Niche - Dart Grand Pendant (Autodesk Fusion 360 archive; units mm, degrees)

design "Dart Grand" references "PCB Single Pendant Canopy"
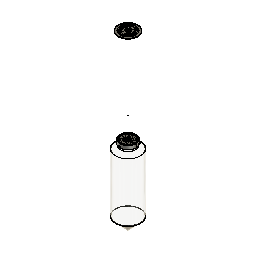
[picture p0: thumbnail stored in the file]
base_feature "Base Feature" bodies "Glass-Dart Grand"
external_derived "ExternalDerived1" bodies "Set Screw", "Strain Relief", "Lead-1", "Lead-2", "Lead-2.1", "Lead-1.1", "Coax", "Stem"
move "Move1"
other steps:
derived_base_feature "Derived Base Feature" bodies "Set Screw", "Strain Relief", "Lead-1", "Lead-2", "Lead-2.1", "Lead-1.1", "Coax", "Stem"
create_component "CreateComponent1"
named bodies: "Glass-Dart Grand", "Set Screw", "Strain Relief", "Lead-1", "Lead-2", "Lead-2.1", "Lead-1.1", "Coax", "Stem", "Strain Relief Cap", "Nylon Gripper (2)", "Cap", "Thumbscrew (1)", "Thumbscrew (2)", "Thumbscrew (3)", "Niche-PCB", "FJ-Plug Cover", "FJ-Plug", "FJ-Plug1.1", "FJ-Plug1.2", "FJ-Plug1.3", "Fj-Plug1.4", "Canopy", "FJ-Port", "FJ-Port1.1", "Spacer", "Universal Mount", "FJ-Port Cover", "Diffuser"

design "FJ Plug - PCB-Hardware"
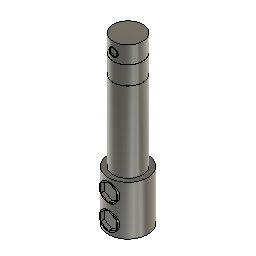
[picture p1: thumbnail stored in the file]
sketch "Sketch1" plane through (0, 0, 0) normal (0, 0, 1) x axis (1, 0, 0)
  circle C1 centre (0, 0) radius 3.048
  point P1 (0, 0)
  point P2 (0, 0)
  coincident P1 P2
  dimension "d1" diameter C1 = 6.096
extrude "Extrude1" new body sketch "Sketch1" along normal blind 34.036
sketch "Sketch2" plane through (0, 0, 0) normal (0, 0, 1) x axis (1, 0, 0)
  circle C1 centre (0, 0) radius 4.064
  point P1 (0, 0)
  point P2 (0, 0)
  coincident P1 P2
  dimension "d4" diameter C1 = 8.128
extrude "Extrude2" add sketch "Sketch2" along normal blind 10.16
sketch "Sketch3" plane through (0, 0, 0) normal (0, 1, 0) x axis (1, 0, 0)
  line L1 (6.35, 0) -> (-6.35, 0)
  line L2 (6.35, -30.48) -> (-6.35, -30.48)
  line L3 (2.54, -30.48) -> (6.35, -30.48)
  line L4 (2.54, -26.67) -> (2.54, -30.48)
  line L5 (6.35, -26.67) -> (2.54, -26.67)
  line L6 (6.35, -30.48) -> (6.35, -26.67)
  horizontal L1
  horizontal L3
  vertical L4
  horizontal L5
  vertical L6
  dimension "d7" = 30.48
revolve "Revolve1" sketch "Sketch3" AlongAngle 360
sketch "Sketch4" plane through (0, 0, 0) normal (0, 1, 0) x axis (1, 0, 0)
  line L1 (2.54, -30.48) -> (3.048, -30.48)
  line L2 (2.54, -26.67) -> (2.54, -30.48)
  line L3 (3.048, -26.67) -> (2.54, -26.67)
  line L4 (3.048, -30.48) -> (3.048, -26.67)
  horizontal L1
  vertical L2
  horizontal L3
  vertical L4
revolve "Revolve2" sketch "Sketch4" AlongAngle 360
chamfer "Chamfer1" distance 0.0254
chamfer "Chamfer2" distance 0.0254
hole "Hole1" HoleDepth 33.401 HoleDiameter 4.826 TipAngle 180
hole "Hole2" HoleDepth 3.81 HoleDiameter 1.778 TipAngle 180
hole "Hole3" HoleDepth 3.81 HoleDiameter 3.81 TipAngle 180
hole "Hole4" HoleDepth 3.81 HoleDiameter 3.81 TipAngle 180
sketch "Sketch5" plane through (0, 0, 0) normal (0, 1, 0) x axis (1, 0, 0)
  circle C1 centre (0, -32.0802) radius 0.889
  dimension "d24" diameter C1 = 1.778
extrude "Extrude3" new body sketch "Sketch5" along normal blind 1.778
move "Move1"
sketch "Sketch6" plane through (0, -3.048, 0) normal (0, -1, 0) x axis (1, 0, 0)
  line L1 (0.7259, 31.6611) -> (0, 31.242)
  line L2 (0.7259, 32.4993) -> (0.7259, 31.6611)
  line L3 (0, 32.9184) -> (0.7259, 32.4993)
  line L4 (-0.7259, 32.4993) -> (0, 32.9184)
  line L5 (-0.7259, 31.6611) -> (-0.7259, 32.4993)
  line L6 (0, 31.242) -> (-0.7259, 31.6611)
  circle C1 centre (0, 32.0802) radius 0.889
  point P2 (0, 32.0802)
  point P9 (0, 32.0802)
  coincident P2 P9
extrude "Extrude4" cut sketch "Sketch6" profile of L1 L2 L3 L4 L5 L6 against normal blind 0.254
sketch "Sketch7" plane through (0, 0, 0) normal (0, 1, 0) x axis (1, 0, 0)
  circle C1 centre (0, -2.4384) radius 1.905
  circle C2 centre (0, -7.5565) radius 1.905
  dimension "d29" diameter C1 = 3.81
  dimension "d30" diameter C2 = 3.81
extrude "Extrude5" new body sketch "Sketch7" profile of C2 along normal blind 3.81
move "Move2"
sketch "Sketch8" plane through (0, -4.064, 0) normal (0, -1, 0) x axis (1, 0, 0)
  line L1 (1.5948, 6.6357) -> (0, 5.715)
  line L2 (1.5948, 8.4772) -> (1.5948, 6.6357)
  line L3 (0, 9.398) -> (1.5948, 8.4772)
  line L4 (-1.5948, 8.4772) -> (0, 9.398)
  line L5 (-1.5948, 6.6357) -> (-1.5948, 8.4772)
  line L6 (0, 5.715) -> (-1.5948, 6.6357)
  circle C1 centre (0, 7.5565) radius 1.905
  point P2 (0, 7.5565)
  point P9 (0, 7.5565)
  coincident P2 P9
extrude "Extrude6" cut sketch "Sketch8" profile of L1 L2 L3 L4 L5 L6 against normal blind 0.762
copy_paste_bodies "CopyPasteBodies2"
move "Move4"
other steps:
base_feature "Base Feature"

design "Flask Petite"
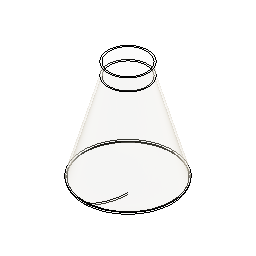
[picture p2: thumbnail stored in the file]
sketch "Sketch1" plane through (0, 0, 0) normal (1, 0, 0) x axis (0, 1, 0)
canvas "Canvas1"
sketch "Sketch2" plane through (0, 0, 0) normal (1, 0, 0) x axis (0, 1, 0)
  line L1 (-5.314, 187.093) -> (-57.384, 187.093)
  line L2 (-57.384, 155.343) -> (-57.384, 187.093)
  line L3 (-121.92, -71.12) -> (-57.384, 155.343)
  line L4 (-5.314, -112.5919) -> (-5.314, 187.093)
  curve K1 (-5.314, -112.5919) -> (-121.92, -74.8854)
  arc A1 centre (-115.3135, -73.0027) radius 6.8695 clockwise from (-121.92, -74.8854) to (-121.92, -71.12)
  point P2 (-57.384, 187.093)
  point P3 (-5.314, 187.093)
  point P4 (-57.384, 155.343)
  horizontal L1
  perpendicular L1 L2
  tangent L3 A1
  perpendicular L1 L4
  dimension "d1" distance P2 P3 = 52.07
  dimension "d2" distance P2 P4 = 31.75
revolve "Revolve1" sketch "Sketch2" AlongAngle 360
fillet "Fillet1" radius 5.08
shell "Shell1" innerThickness 4

design "PCB Single Pendant Canopy" references "Flask Petite", "FJ Cover - PCB-Hardware", "PCB Cap", "PCB Canopy", "Diffuser", "FJ Plug - PCB-Hardware"
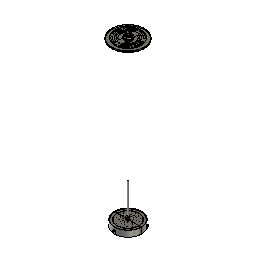
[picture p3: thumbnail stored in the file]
external_derived "ExternalDerived1" bodies "Nylon Gripper", "Set Screw", "Strain Relief", "Lead-1", "Lead-2", "Lead-2.1", "Lead-1.1", "Coax"
external_derived "ExternalDerived2" bodies "FJ-Plug Cover"
move "Move1"
move "Move2" TranslateX 3.175 TranslateY 0.254 TranslateZ 0
move "Move3" TranslateX 0 TranslateY 0 TranslateZ 1092.2
external_derived "ExternalDerived3" bodies "FJ-Plug", "FJ-Plug1.2", "FJ-Plug1.1", "FJ-Plug1.3", "Fj-Plug1.4"
move "Move4" TranslateX 0 TranslateY 0 TranslateZ 1117.6
external_derived "ExternalDerived4" bodies "Nylon Gripper", "Spacer", "Canopy", "FJ-Port", "FJ-Port1.1", "Universal Mount", "FJ-Port Cover", "Lead-1.1"
move "Move5"
move "Move6"
external_derived "ExternalDerived5" bodies "Diffuser"
move "Move7"
external_derived "ExternalDerived6" bodies "Thumbscrew (1)"
align "Align1"
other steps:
derived_base_feature "Derived Base Feature1"
derived_base_feature "Derived Base Feature2" bodies "FJ-Plug Cover"
derived_base_feature "Derived Base Feature3" bodies "FJ-Plug", "FJ-Plug1.1", "FJ-Plug1.2"
derived_base_feature "Derived Base Feature4" bodies "Body1 (1)", "Body1 (1) (1)", "Body2 (1)", "Body1 (2)", "Body1 (3)", "Body1 (4)", "Canopy", "FJ-Port"
derived_base_feature "Derived Base Feature5" bodies "Diffuser"
derived_base_feature "Derived Base Feature6" bodies "Body1", "Thumbscrew (1)"
named bodies: "Nylon Gripper", "Set Screw", "Strain Relief", "Lead-1", "Lead-2", "Lead-2.1", "Lead-1.1", "Coax", "Stem", "stem (2)", "Strain Relief Cap", "Nylon Gripper (2)", "Cap", "Thumbscrew (1)", "Thumbscrew (2)", "Thumbscrew (3)", "Niche-PCB", "FJ-Plug Cover", "FJ-Plug", "FJ-Plug1.1", "FJ-Plug1.2", "FJ-Plug1.3", "Fj-Plug1.4", "Body1 (1)", "Body1 (1) (1)", "Body2 (1)", "Body1 (2)", "Body1 (3)", "Body1 (4)", "Canopy", "FJ-Port", "FJ-Port1.1", "Spacer", "Universal Mount", "FJ-Port Cover", "Diffuser", "Body1"

design "FJ Female"
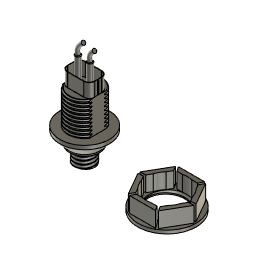
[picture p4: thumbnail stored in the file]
sketch "Sketch1" plane through (0, 0, 0) normal (0, 0, 1) x axis (1, 0, 0)
  circle C1 centre (0, 0) radius 4.445
  point P1 (0, 0)
  point P2 (0, 0)
  coincident P1 P2
  dimension "d1" diameter C1 = 8.89
extrude "Extrude1" new body sketch "Sketch1" along normal blind 6.858
sketch "Sketch2" plane through (0, 0, 6.858) normal (0, 0, 1) x axis (-1, 0, 0)
  circle C1 centre (0, 0) radius 4.445
  circle C2 centre (0, 0) radius 6.985
  point P1 (0, 0)
  point P3 (0, 0)
  coincident P1 P3
  dimension "d4" diameter C2 = 13.97
extrude "Extrude2" add sketch "Sketch2" along normal blind 1.27
work_plane "WorkPlane1" AlongDistance 5.08
sketch "Sketch3" plane through (0, 0, 13.208) normal (0, 0, 1) x axis (1, 0, 0)
  circle C1 centre (0, 0) radius 11.43
  point P1 (0, 0)
  point P2 (0, 0)
  coincident P1 P2
  dimension "d8" diameter C1 = 22.86
loft "Loft1" sketch "Sketch3"
extrude "Extrude3" add of existing geometry blind 1.778
sketch "Sketch4" plane through (0, 0, 14.986) normal (0, 0, 1) x axis (-1, 0, 0)
  circle C1 centre (0, 0) radius 11.43
  circle C2 centre (0, 0) radius 7.62
  point P1 (0, 0)
  point P3 (0, 0)
  coincident P1 P3
  dimension "d11" diameter C2 = 15.24
extrude "Extrude4" add sketch "Sketch4" profile of C2 along normal blind 15.24
sketch "Sketch5" plane through (0, 0, 30.226) normal (0, 0, 1) x axis (-1, 0, 0)
  line L1 (6.35, 0) -> (0, 0)
  line L2 (-6.35, 0) -> (0, 0)
  line L3 (6.35, -4.2121) -> (6.35, 0)
  line L4 (6.35, 4.2121) -> (6.35, 0)
  line L5 (-6.35, -4.2121) -> (-6.35, 0)
  line L6 (-6.35, 4.2121) -> (-6.35, 0)
  circle C1 centre (0, 0) radius 7.62
  point P2 (0, 0)
  point P3 (0, 0)
  point P5 (0, 0)
  point P7 (6.35, -4.2121)
  point P8 (6.35, 4.2121)
  point P9 (-6.35, -4.2121)
  point P10 (-6.35, 0)
  point P11 (-6.35, 4.2121)
  point P4 (6.35, 0)
  point P6 (-6.35, 0)
  coincident P2 P3
  horizontal L1
  coincident P2 P5
  parallel L1 L2
  coincident C1 P7
  perpendicular L1 L3
  coincident C1 P8
  perpendicular L1 L4
  coincident C1 P9
  perpendicular L2 L5
  coincident L2 P10
  perpendicular L2 L6
  coincident C1 P11
  dimension "d14" distance P3 P4 = 6.35
  dimension "d15" distance P5 P6 = 6.35
extrude "Extrude5" cut sketch "Sketch5" profile of C1 L3 L4 L5 L6 against normal blind 15.24
sketch "Sketch6" plane through (0, 0, 30.226) normal (0, 0, 1) x axis (-1, 0, 0)
  line L1 (-6.35, -4.2121) -> (-6.35, 4.2121)
  line L2 (6.35, 4.2121) -> (6.35, -4.2121)
  line L3 (-6.35, -4.2121) -> (6.35, -4.2121)
  line L4 (6.35, 4.2121) -> (-6.35, 4.2121)
  line L5 (6.35, -4.2121) -> (6.35, 4.2121)
  line L6 (-6.35, 4.2121) -> (-6.35, -4.2121)
  line L7 (-6.223, 4.064) -> (6.223, 4.064)
  line L8 (-6.223, -4.064) -> (-6.223, 4.064)
  line L9 (6.223, -4.064) -> (-6.223, -4.064)
  line L10 (6.223, 4.064) -> (6.223, -4.064)
  line L11 (-6.223, -4.064) -> (6.223, 4.064)
  line L12 (6.223, -4.064) -> (-6.223, 4.064)
  arc A1 centre (0, 0) radius 7.62 clockwise from (6.35, -4.2121) to (-6.35, -4.2121)
  arc A2 centre (0, 0) radius 7.62 clockwise from (-6.35, 4.2121) to (6.35, 4.2121)
  point P4 (6.35, -4.2121)
  point P7 (6.35, -4.2121)
  point P3 (-6.35, -4.2121)
  point P8 (-6.35, -4.2121)
  point P2 (-6.35, 4.2121)
  point P9 (-6.35, 4.2121)
  point P6 (6.35, 4.2121)
  point P10 (6.35, 4.2121)
  point P15 (0, 0)
  point P5 (0, 0)
  point P13 (-6.223, -4.064)
  point P14 (6.223, -4.064)
  point P12 (-6.223, 4.064)
  coincident P4 P7
  coincident P3 P8
  coincident P2 P9
  coincident P6 P10
  perpendicular L7 L8
  parallel L7 L9
  parallel L8 L10
  horizontal L7
  coincident L11 P15
  coincident L12 P15
  coincident P5 P15
  dimension "d18" distance P13 P14 = 12.446
  dimension "d19" distance P12 P13 = 8.128
extrude "Extrude6" add sketch "Sketch6" profile of L1 L2 L3 L4 L5 L6 L7 L8 L9 L10 along normal blind 6.35
fillet "Fillet1" radius 2.54
sketch "Sketch7" plane through (6.35, 0, 0) normal (1, 0, 0) x axis (0, 1, 0)
  line L1 (1.6721, 36.576) -> (1.6721, 30.226)
  line L2 (-1.6721, 36.576) -> (1.6721, 36.576)
  line L3 (-1.6721, 30.226) -> (-1.6721, 36.576)
  line L4 (-4.2121, 30.226) -> (-1.6721, 30.226)
  line L5 (-4.2121, 14.986) -> (-4.2121, 30.226)
  line L6 (4.2121, 14.986) -> (-4.2121, 14.986)
  line L7 (4.2121, 30.226) -> (4.2121, 14.986)
  line L8 (1.6721, 30.226) -> (4.2121, 30.226)
  line L9 (0.254, 36.576) -> (-0.2492, 36.576)
  line L10 (0.254, 30.226) -> (0.254, 36.576)
  line L11 (-0.2492, 30.226) -> (0.254, 30.226)
  line L12 (-0.2492, 36.576) -> (-0.2492, 30.226)
  point P10 (-0.2492, 36.576)
  horizontal L9
  vertical L10
  horizontal L11
  vertical L12
  coincident L2 P10
extrude "Extrude7" cut sketch "Sketch7" profile of L2 L9 L10 L11 L12 against normal blind 0.508
thread "Thread1"
fillet "Fillet2" radius 0.635
thread "Thread2"
sketch "Sketch8" plane through (0, 0, 30.226) normal (0, 0, 1) x axis (-1, 0, 0)
  line L1 (-6.223, -1.524) -> (-6.223, -0.254)
  line L2 (3.683, -4.064) -> (-3.683, -4.064)
  line L3 (6.223, 1.524) -> (6.223, -1.524)
  line L4 (-3.683, 4.064) -> (3.683, 4.064)
  line L5 (-6.223, 0.2492) -> (-6.223, 1.524)
  line L6 (-6.35, 0.2492) -> (-6.223, 0.2492)
  line L7 (-6.35, -0.254) -> (-6.35, 0.2492)
  line L8 (-6.223, -0.254) -> (-6.35, -0.254)
  arc A1 centre (-3.683, -1.524) radius 2.54 clockwise from (-3.683, -4.064) to (-6.223, -1.524)
  arc A2 centre (3.683, -1.524) radius 2.54 clockwise from (6.223, -1.524) to (3.683, -4.064)
  arc A3 centre (3.683, 1.524) radius 2.54 clockwise from (3.683, 4.064) to (6.223, 1.524)
  arc A4 centre (-3.683, 1.524) radius 2.54 clockwise from (-6.223, 1.524) to (-3.683, 4.064)
  circle C1 centre (3.048, 0) radius 1.27
  circle C2 centre (-2.54, 0) radius 1.27
  dimension "d26" diameter C1 = 2.54
  dimension "d27" diameter C2 = 2.54
extrude "Extrude8" add sketch "Sketch8" profile of C1 C2 along normal blind 11.43
sketch "Sketch9" plane through (0, 0, 0) normal (0, 1, 0) x axis (1, 0, 0)
  curve K1 (4.572, -46.99) -> (2.54, -41.656)
  curve K2 (-0.508, -47.752) -> (-3.048, -41.656)
pipe "Pipe1" SectionSize 1.778 SectionThickness 0.0762
pipe "Pipe2" SectionSize 1.778 SectionThickness 0.0762
sketch "Sketch10" plane through (0, 0, 0) normal (0, 0, 1) x axis (1, 0, 0)
  circle C1 centre (38.1, 0) radius 13.462
  dimension "d38" diameter C1 = 26.924
extrude "Extrude9" new body sketch "Sketch10" along normal blind 1.524
sketch "Sketch11" plane through (0, 0, 1.524) normal (0, 0, 1) x axis (-1, 0, 0)
  circle C1 centre (-38.1, 0) radius 13.462
  circle C2 centre (-38.1, 0) radius 9.271
  concentric C1 C2
  dimension "d41" diameter C2 = 18.542
extrude "Extrude10" cut sketch "Sketch11" profile of C2 against normal blind 7.62
sketch "Sketch12" plane through (0, 0, 1.524) normal (0, 0, 1) x axis (-1, 0, 0)
  line L1 (-24.9018, 0) -> (-31.5009, -11.43)
  line L2 (-31.5009, 11.43) -> (-24.9018, 0)
  line L3 (-44.6991, 11.43) -> (-31.5009, 11.43)
  line L4 (-51.2982, 0) -> (-44.6991, 11.43)
  line L5 (-44.6991, -11.43) -> (-51.2982, 0)
  line L6 (-31.5009, -11.43) -> (-44.6991, -11.43)
  line L7 (-27.3948, 0) -> (-32.7474, -9.271)
  line L8 (-32.7474, 9.271) -> (-27.3948, 0)
  line L9 (-43.4526, 9.271) -> (-32.7474, 9.271)
  line L10 (-48.8052, 0) -> (-43.4526, 9.271)
  line L11 (-43.4526, -9.271) -> (-48.8052, 0)
  line L12 (-32.7474, -9.271) -> (-43.4526, -9.271)
  circle C1 centre (-38.1, 0) radius 9.271
  circle C2 centre (-38.1, 0) radius 13.462
  point P2 (-38.1, 0)
  point P9 (-38.1, 0)
  point P16 (-38.1, 0)
  coincident P2 P9
  coincident P9 P16
extrude "Extrude11" add sketch "Sketch12" profile of L1 L2 L3 L4 L5 L6 L7 L8 L9 L10 L11 L12 along normal blind 7.112
thread "Thread3"
sketch "Sketch13" plane through (0, 0, 8.636) normal (0, 0, 1) x axis (-1, 0, 0)
  line L1 (-43.4526, -9.271) -> (-32.7474, -9.271)
  line L2 (-48.8052, 0) -> (-43.4526, -9.271)
  line L3 (-43.4526, 9.271) -> (-48.8052, 0)
  line L4 (-32.7474, 9.271) -> (-43.4526, 9.271)
  line L5 (-27.3948, 0) -> (-32.7474, 9.271)
  line L6 (-32.7474, -9.271) -> (-27.3948, 0)
  line L7 (-31.5009, -11.43) -> (-44.6991, -11.43)
  line L8 (-24.9018, 0) -> (-31.5009, -11.43)
  line L9 (-31.5009, 11.43) -> (-24.9018, 0)
  line L10 (-44.6991, 11.43) -> (-31.5009, 11.43)
  line L11 (-51.2982, 0) -> (-44.6991, 11.43)
  line L12 (-44.6991, -11.43) -> (-51.2982, 0)
sketch "Sketch14" plane through (0, 0, 8.636) normal (0, 0, 1) x axis (-1, 0, 0)
  circle C1 centre (-38.1, 0) radius 9.525
  dimension "d46" diameter C1 = 19.05
extrude "Extrude12" cut sketch "Sketch14" against normal blind 7.112
sketch "Sketch15" plane through (0, 0, 8.636) normal (0, 0, 1) x axis (-1, 0, 0)
  line L1 (-51.2982, 0) -> (-44.6991, 11.43)
  line L2 (-43.4526, 9.271) -> (-48.8052, 0)
  line L3 (-32.7474, 9.271) -> (-43.4526, 9.271)
  line L4 (-44.6991, 11.43) -> (-31.5009, 11.43)
  line L5 (-44.1911, 11.43) -> (-42.7995, 9.271)
  line L6 (-40.2139, 9.271) -> (-42.7995, 9.271)
  line L7 (-43.7181, 8.8112) -> (-45.0232, 10.8687)
  line L8 (-43.4526, 9.271) -> (-42.7995, 9.271)
  line L9 (-43.7181, 8.8112) -> (-43.4526, 9.271)
  line L10 (-45.0232, 10.8687) -> (-44.6991, 11.43)
  line L11 (-44.1911, 11.43) -> (-44.6991, 11.43)
  line L12 (-48.5398, -0.4598) -> (-50.9742, -0.5613)
  line L13 (-48.5398, -0.4598) -> (-48.8052, 0)
  line L14 (-48.8052, 0) -> (-48.4787, 0.5657)
  line L15 (-51.0442, 0.4399) -> (-48.4787, 0.5657)
  line L16 (-51.0442, 0.4399) -> (-51.2982, 0)
  line L17 (-50.9742, -0.5613) -> (-51.2982, 0)
  line L18 (-42.9217, -9.271) -> (-44.051, -11.43)
  line L19 (-42.9217, -9.271) -> (-43.4526, -9.271)
  line L20 (-43.4526, -9.271) -> (-43.7792, -8.7053)
  line L21 (-44.9531, -10.9901) -> (-43.7792, -8.7053)
  line L22 (-44.9531, -10.9901) -> (-44.6991, -11.43)
  line L23 (-44.051, -11.43) -> (-44.6991, -11.43)
  line L24 (-32.4819, -8.8112) -> (-31.1768, -10.8687)
  line L25 (-32.4819, -8.8112) -> (-32.7474, -9.271)
  line L26 (-32.7474, -9.271) -> (-33.4005, -9.271)
  line L27 (-32.0089, -11.43) -> (-33.4005, -9.271)
  line L28 (-32.0089, -11.43) -> (-31.5009, -11.43)
  line L29 (-31.1768, -10.8687) -> (-31.5009, -11.43)
  line L30 (-27.6603, 0.4598) -> (-25.2258, 0.5613)
  line L31 (-27.6603, 0.4598) -> (-27.3948, 0)
  line L32 (-27.3948, 0) -> (-27.7214, -0.5657)
  line L33 (-25.1558, -0.4399) -> (-27.7214, -0.5657)
  line L34 (-25.1558, -0.4399) -> (-24.9018, 0)
  line L35 (-25.2258, 0.5613) -> (-24.9018, 0)
  line L36 (-33.2783, 9.271) -> (-32.149, 11.43)
  line L37 (-33.2783, 9.271) -> (-32.7474, 9.271)
  line L38 (-32.7474, 9.271) -> (-32.4208, 8.7053)
  line L39 (-31.2469, 10.9901) -> (-32.4208, 8.7053)
  line L40 (-31.2469, 10.9901) -> (-31.5009, 11.43)
  line L41 (-32.149, 11.43) -> (-31.5009, 11.43)
  point P10 (-42.7995, 9.271)
  point P12 (-45.0232, 10.8687)
  point P13 (-43.7181, 8.8112)
  point P5 (-43.4526, 9.271)
  point P14 (-43.4526, 9.271)
  point P16 (-44.1911, 11.43)
  point P9 (-44.6991, 11.43)
  point P15 (-44.6991, 11.43)
  horizontal L6
  coincident L3 P10
  coincident L1 P12
  coincident L2 P13
  coincident P5 P14
  coincident L4 P16
  coincident P9 P15
  coincident L4 P16
  dimension "d50" distance P15 P16 = 0.508
  dimension "d54" C-Pattern1-Angle = 360
extrude "Extrude13" cut sketch "Sketch15" profile of L1 L2 L3 L4 L5 L7 L8 L9 L10 L11 L12 L13 L14 L15 L16 L17 L18 L19 L20 L21 L22 L23 L24 L25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 against normal blind 7.112

design "FJ Cover - PCB-Hardware"
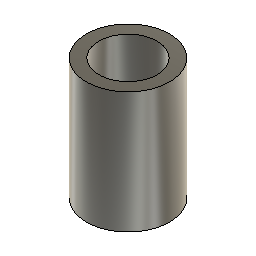
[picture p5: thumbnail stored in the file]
sketch "Sketch1" plane through (0, 0, 0) normal (0, 0, 1) x axis (1, 0, 0)
  circle C1 centre (0, 0) radius 6.35
  point P1 (0, 0)
  point P2 (0, 0)
  coincident P1 P2
  dimension "d1" diameter C1 = 12.7
extrude "Extrude1" new body sketch "Sketch1" along normal blind 18.542
hole "Hole1" HoleDepth 13.97 HoleDiameter 8.89 TipAngle 180
hole "Hole2" HoleDepth 13.97 HoleDiameter 3.556 TipAngle 180

design "PCB Canopy" references "Universal Mounting Bracket - PCB-Hardware", "FJ Female", "Canopy - PCB-Hardware", "Port Cover - PCB-Hardware", "FJ Cover - PCB-Hardware", "Spacer - PCB-Hardware"
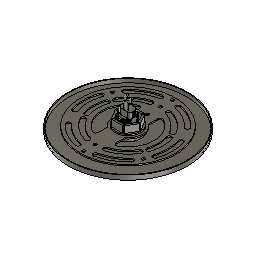
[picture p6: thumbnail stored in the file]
external_derived "ExternalDerived"
external_derived "ExternalDerived"
external_derived "ExternalDerived3" bodies "Body1 (1)"
external_derived "ExternalDerived4"
external_derived "ExternalDerived5"
move "Move1"
move "Move2"
move "Move3"
move "Move4"
move "Move5"
move "Move6"
move "Move7"
move "Move8"
external_derived "ExternalDerived6"
align "Align1"
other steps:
derived_base_feature "Derived Base Feature" bodies "Body1"
derived_base_feature "Derived Base Feature" bodies "Body1 (1)", "Body2"
derived_base_feature "Derived Base Feature3" bodies "Body1 (2)", "Body1 (1)"
derived_base_feature "Derived Base Feature4" bodies "Body1 (3)"
derived_base_feature "Derived Base Feature5" bodies "Body1 (4)"
derived_base_feature "Derived Base Feature6" bodies "Body1 (5)"
named bodies: "Body1", "Body1 (1)", "Body2", "Body1 (2)", "Body1 (3)", "Body1 (4)", "Body1 (5)"

design "Spacer - PCB-Hardware"
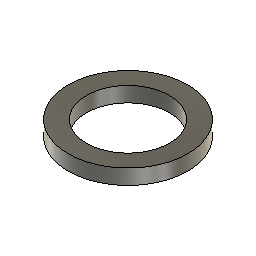
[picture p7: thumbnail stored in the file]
sketch "Sketch1" plane through (0, 0, 0) normal (0, 0, 1) x axis (1, 0, 0)
  circle C1 centre (0, 0) radius 14.097
  circle C2 centre (0, 0) radius 9.779
  point P1 (0, 0)
  point P2 (0, 0)
  point P3 (0, 0)
  coincident P1 P2
  coincident P1 P3
  dimension "d1" diameter C1 = 28.194
  dimension "d2" diameter C2 = 19.558
extrude "Extrude1" new body sketch "Sketch1" along normal blind 3.556

design "Universal Mounting Bracket - PCB-Hardware"
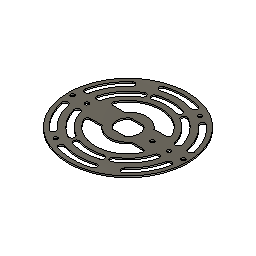
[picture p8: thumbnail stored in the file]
sketch "Sketch1" plane through (0, 0, 0) normal (0, 0, 1) x axis (1, 0, 0)
  circle C1 centre (0, 0) radius 50.8
  arc A1 centre (0, 0) radius 42.545 clockwise from (-13.1471, 40.4627) to (13.1471, 40.4627)
  arc A2 centre (0, 0) radius 47.371 clockwise from (-14.6384, 45.0525) to (14.6384, 45.0525)
  arc A3 centre (-13.8928, 42.7576) radius 2.413 clockwise from (-13.1471, 40.4627) to (-14.6384, 45.0525)
  arc A4 centre (13.8928, 42.7576) radius 2.413 clockwise from (14.6384, 45.0525) to (13.1471, 40.4627)
  arc A5 centre (0, 0) radius 47.371 clockwise from (-46.3358, 9.849) to (-31.6974, 35.2035)
  arc A6 centre (0, 0) radius 42.545 clockwise from (-41.6153, 8.8456) to (-28.4682, 31.6171)
  arc A7 centre (-43.9756, 9.3473) radius 2.413 clockwise from (-41.6153, 8.8456) to (-46.3358, 9.849)
  arc A8 centre (-30.0828, 33.4103) radius 2.413 clockwise from (-31.6974, 35.2035) to (-28.4682, 31.6171)
  arc A9 centre (0, 0) radius 47.371 clockwise from (-31.6974, -35.2035) to (-46.3358, -9.849)
  arc A10 centre (0, 0) radius 42.545 clockwise from (-28.4682, -31.6171) to (-41.6153, -8.8456)
  arc A11 centre (-30.0828, -33.4103) radius 2.413 clockwise from (-28.4682, -31.6171) to (-31.6974, -35.2035)
  arc A12 centre (-43.9756, -9.3473) radius 2.413 clockwise from (-46.3358, -9.849) to (-41.6153, -8.8456)
  arc A13 centre (0, 0) radius 47.371 clockwise from (14.6384, -45.0525) to (-14.6384, -45.0525)
  arc A14 centre (0, 0) radius 42.545 clockwise from (13.1471, -40.4627) to (-13.1471, -40.4627)
  arc A15 centre (13.8928, -42.7576) radius 2.413 clockwise from (13.1471, -40.4627) to (14.6384, -45.0525)
  arc A16 centre (-13.8928, -42.7576) radius 2.413 clockwise from (-14.6384, -45.0525) to (-13.1471, -40.4627)
  arc A17 centre (0, 0) radius 47.371 clockwise from (46.3358, -9.849) to (31.6974, -35.2035)
  arc A18 centre (0, 0) radius 42.545 clockwise from (41.6153, -8.8456) to (28.4682, -31.6171)
  arc A19 centre (43.9756, -9.3473) radius 2.413 clockwise from (41.6153, -8.8456) to (46.3358, -9.849)
  arc A20 centre (30.0828, -33.4103) radius 2.413 clockwise from (31.6974, -35.2035) to (28.4682, -31.6171)
  arc A21 centre (0, 0) radius 47.371 clockwise from (31.6974, 35.2035) to (46.3358, 9.849)
  arc A22 centre (0, 0) radius 42.545 clockwise from (28.4682, 31.6171) to (41.6153, 8.8456)
  arc A23 centre (30.0828, 33.4103) radius 2.413 clockwise from (28.4682, 31.6171) to (31.6974, 35.2035)
  arc A24 centre (43.9756, 9.3473) radius 2.413 clockwise from (46.3358, 9.849) to (41.6153, 8.8456)
  arc A25 centre (0, 0) radius 32.385 clockwise from (-31.2224, 8.5995) to (-16.1925, 28.0462)
  arc A26 centre (0, 0) radius 37.338 clockwise from (-35.9514, 10.0809) to (-18.669, 32.3357)
  arc A27 centre (0, 0) radius 32.385 clockwise from (16.1925, 28.0462) to (31.2224, 8.5995)
  arc A28 centre (0, 0) radius 32.385 clockwise from (-10.0075, 30.8) to (10.0075, 30.8)
  arc A29 centre (0, 0) radius 37.338 clockwise from (18.669, 32.3357) to (35.9514, 10.0809)
  arc A30 centre (0, 0) radius 37.338 clockwise from (-11.5381, 35.5105) to (11.5381, 35.5105)
  arc A31 centre (-33.5467, 9.4685) radius 2.4814 clockwise from (-31.1111, 8.9939) to (-35.9167, 10.2037)
  arc A32 centre (-17.4307, 30.1909) radius 2.4765 clockwise from (-18.669, 32.3357) to (-16.1925, 28.0462)
  arc A33 centre (-10.7728, 33.1553) radius 2.4765 clockwise from (-10.0075, 30.8) to (-11.5381, 35.5105)
  arc A34 centre (10.7728, 33.1553) radius 2.4765 clockwise from (11.5381, 35.5105) to (10.0075, 30.8)
  arc A35 centre (17.4307, 30.1909) radius 2.4765 clockwise from (16.1925, 28.0462) to (18.669, 32.3357)
  arc A36 centre (33.5467, 9.4685) radius 2.4814 clockwise from (35.9167, 10.2037) to (31.1111, 8.9939)
  arc A37 centre (-33.5467, -9.4685) radius 2.4814 clockwise from (-35.9167, -10.2037) to (-31.1111, -8.9939)
  arc A38 centre (0, 0) radius 37.338 clockwise from (-18.669, -32.3357) to (-35.9514, -10.0809)
  arc A39 centre (0, 0) radius 32.385 clockwise from (-16.1925, -28.0462) to (-31.2224, -8.5995)
  arc A40 centre (-17.4307, -30.1909) radius 2.4765 clockwise from (-16.1925, -28.0462) to (-18.669, -32.3357)
  arc A41 centre (-10.7728, -33.1553) radius 2.4765 clockwise from (-11.5381, -35.5105) to (-10.0075, -30.8)
  arc A42 centre (0, 0) radius 37.338 clockwise from (11.5381, -35.5105) to (-11.5381, -35.5105)
  arc A43 centre (0, 0) radius 32.385 clockwise from (10.0075, -30.8) to (-10.0075, -30.8)
  arc A44 centre (10.7728, -33.1553) radius 2.4765 clockwise from (10.0075, -30.8) to (11.5381, -35.5105)
  arc A45 centre (17.4307, -30.1909) radius 2.4765 clockwise from (18.669, -32.3357) to (16.1925, -28.0462)
  arc A46 centre (0, 0) radius 37.338 clockwise from (35.9514, -10.0809) to (18.669, -32.3357)
  arc A47 centre (0, 0) radius 32.385 clockwise from (31.2224, -8.5995) to (16.1925, -28.0462)
  arc A48 centre (33.5467, -9.4685) radius 2.4814 clockwise from (31.1111, -8.9939) to (35.9167, -10.2037)
  point P1 (0, 0)
  point P2 (0, 0)
  point P71 (-35.9514, 10.0809)
  point P72 (-31.2224, 8.5995)
  point P73 (35.9514, 10.0809)
  point P74 (31.2224, 8.5995)
  point P75 (-31.1111, 8.9939)
  point P76 (-35.9167, 10.2037)
  point P77 (35.9167, 10.2037)
  point P78 (31.1111, 8.9939)
  coincident P1 P2
  concentric C1 A2
  concentric A1 A2
  concentric A17 A26
  concentric A25 A26
  concentric A25 A27
  concentric A26 A29
  concentric A27 A28
  concentric A29 A30
  coincident P71 A31
  coincident P72 A31
  coincident P73 A36
  coincident P74 A36
  coincident A25 P75
  coincident A26 P76
  coincident A29 P77
  coincident A27 P78
  dimension "d1" diameter C1 = 101.6
  dimension "d2" diameter A2 = 94.742
  dimension "d11" diameter A26 = 74.676
  dimension "d12" diameter A25 = 64.77
  dimension "d10" C-Pattern1-Angle = 360
sketch "Sketch2" plane through (0, 0, 0) normal (0, 0, 1) x axis (1, 0, 0)
  line L1 (5.3986, -8.001) -> (-5.3986, -8.001)
  line L2 (5.3986, 8.001) -> (-5.3986, 8.001)
  arc A1 centre (0, 0) radius 9.652 clockwise from (-5.3986, -8.001) to (-5.3986, 8.001)
  arc A2 centre (0, 0) radius 9.652 clockwise from (5.3986, 8.001) to (5.3986, -8.001)
  point P1 (0, 0)
  point P2 (0, 0)
  coincident P1 P2
  concentric A1 A2
  dimension "d6" diameter A1 = 19.304
sketch "Sketch3" plane through (0, 0, 0) normal (0, 0, 1) x axis (1, 0, 0)
  line L1 (-12.5409, 9.525) -> (-22.2072, 9.525)
  line L2 (22.2072, 9.525) -> (12.5409, 9.525)
  line L3 (-12.5409, -9.525) -> (-22.2072, -9.525)
  line L4 (22.2072, -9.525) -> (12.5409, -9.525)
  arc A1 centre (0, 0) radius 15.748 clockwise from (12.5409, -9.525) to (-12.5409, -9.525)
  arc A2 centre (0, 0) radius 15.748 clockwise from (-12.5409, 9.525) to (12.5409, 9.525)
  arc A3 centre (0, 0) radius 27.813 clockwise from (24.4391, -13.2776) to (-24.4391, -13.2776)
  arc A4 centre (0, 0) radius 27.813 clockwise from (-24.4391, 13.2776) to (24.4391, 13.2776)
  arc A5 centre (-22.2072, 12.065) radius 2.54 clockwise from (-22.2072, 9.525) to (-24.4391, 13.2776)
  arc A6 centre (22.2072, 12.065) radius 2.54 clockwise from (24.4391, 13.2776) to (22.2072, 9.525)
  arc A7 centre (-22.2072, -12.065) radius 2.54 clockwise from (-24.4391, -13.2776) to (-22.2072, -9.525)
  arc A8 centre (22.2072, -12.065) radius 2.54 clockwise from (22.2072, -9.525) to (24.4391, -13.2776)
  point P1 (0, 0)
  point P2 (0, 0)
  point P5 (12.5409, 9.525)
  coincident P1 P2
  concentric A1 A3
  coincident P5 A1
  collinear L1 L2
  collinear L3 L4
  concentric A1 A2
  concentric A3 A4
  tangent L1 A5
  tangent A4 A5
  tangent L2 A6
  tangent A4 A6
  equal A5 A6
  tangent L3 A7
  tangent A3 A7
  equal A5 A7
  tangent L4 A8
  tangent A3 A8
  equal A5 A8
  dimension "d17" diameter A3 = 55.626
  dimension "d18" diameter A1 = 31.496
  dimension "d37" radius A5 = 2.54
sketch "Sketch4" plane through (0, 0, 0) normal (0, 0, 1) x axis (1, 0, 0)
  circle C1 centre (22.479, 38.9348) radius 1.651
  circle C2 centre (-22.479, -38.9348) radius 1.651
  circle C3 centre (-34.8615, 0) radius 1.651
  circle C4 centre (-47.117, 0) radius 1.651
  circle C5 centre (34.8615, 0) radius 1.651
  circle C6 centre (47.117, 0) radius 1.651
  circle C7 centre (20.701, 0) radius 1.651
  dimension "d36" diameter C7 = 3.302
  dimension "d25" C-Pattern2-Angle = 180
extrude "Extrude1" new body sketch "Sketch1" profile of C1 A2 A1 A3 A4 A5 A6 A7 A8 A9 A10 A11 A12 A13 A14 A15 A16 A17 A18 A19 A20 A21 A22 A23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 along normal blind 1.27
extrude "Extrude2" cut sketch "Sketch3" + "Sketch2" profile of S2:A2 S2:L1 S2:L2 S1:A4 S1:A2 S1:L4 S1:L2 S1:A5 S1:A6 S1:A7 S1:A8 blind 1.27
extrude "Extrude3" cut sketch "Sketch4" along normal blind 1.27

design "Port Cover - PCB-Hardware"
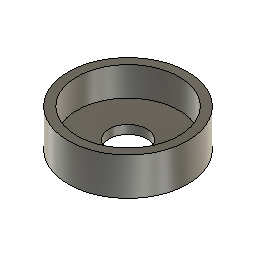
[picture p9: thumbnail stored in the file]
sketch "Sketch1" plane through (0, 0, 0) normal (0, 0, 1) x axis (1, 0, 0)
  circle C1 centre (0, 0) radius 14.097
  point P1 (0, 0)
  point P2 (0, 0)
  coincident P1 P2
  dimension "d1" diameter C1 = 28.194
extrude "Extrude1" new body sketch "Sketch1" along normal blind 8.89
shell "Shell1" innerThickness 2.032
hole "Hole1" HoleDepth 22.86 HoleDiameter 8.89 TipAngle 118

design "PCB Cap"
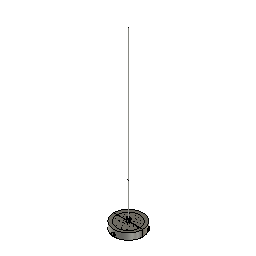
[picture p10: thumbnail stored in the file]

design "Canopy - PCB-Hardware"
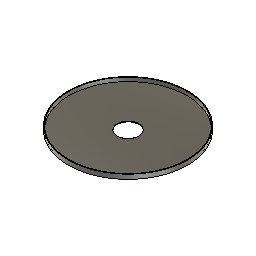
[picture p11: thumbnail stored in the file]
sketch "Sketch1" plane through (0, 0, 0) normal (0, 0, 1) x axis (1, 0, 0)
  circle C1 centre (0, 0) radius 63.5
  point P1 (0, 0)
  point P2 (0, 0)
  coincident P1 P2
extrude "Extrude1" new body sketch "Sketch1" along normal blind 4.826
shell "Shell1" innerThickness 0.762
hole "Hole1" HoleDepth 22.86 HoleDiameter 22.86 TipAngle 118

design "Diffuser"
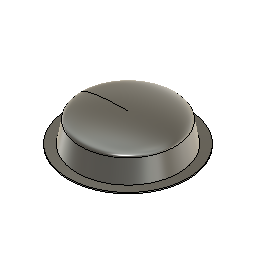
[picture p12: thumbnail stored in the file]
sketch "Sketch1" plane through (0, 0, 0) normal (0, 1, 0) x axis (1, 0, 0)
sketch "Sketch2" plane through (0, 0, 0) normal (0, 0, 1) x axis (1, 0, 0)
  circle C1 centre (0, 0) radius 43.18
  point P1 (0, 0)
  point P2 (0, 0)
  coincident P1 P2
  dimension "d1" diameter C1 = 86.36
sketch "Sketch4" plane through (0, 0, 0) normal (0, 0, 1) x axis (1, 0, 0)
  circle C1 centre (0, 0) radius 50.8
  point P1 (0, 0)
  point P2 (0, 0)
  coincident P1 P2
  dimension "d2" diameter C1 = 101.6
extrude "Extrude1" new body sketch "Sketch4" along normal blind 1.016
sketch "Sketch5" plane through (0, 0, 1.016) normal (0, 0, 1) x axis (-1, 0, 0)
  circle C1 centre (0, 0) radius 50.8
  circle C2 centre (0, 0) radius 42.545
  concentric C1 C2
  dimension "d5" diameter C2 = 85.09
sketch "Sketch8" plane through (0, 0, 1.016) normal (0, 0, 1) x axis (-1, 0, 0)
  circle C1 centre (0, 0) radius 42.545
sketch "Sketch11" plane through (0, 0, 0) normal (0, 1, 0) x axis (1, 0, 0)
sketch "Sketch14" plane through (0, 0, 0) normal (0, 1, 0) x axis (1, 0, 0)
sketch "Sketch15" plane through (0, 0, 1.016) normal (0, 0, 1) x axis (-1, 0, 0)
  line L1 (-42.545, 0) -> (0, 0)
  circle C1 centre (0, 0) radius 42.545
  point P1 (0, 0)
  point P3 (0, 0)
  point P4 (-42.545, 0)
  coincident P1 P3
  coincident C1 P4
  horizontal L1
sketch "Sketch16" plane through (0, 0, 0) normal (0, 0, -1) x axis (1, 0, 0)
  circle C1 centre (0, 0) radius 50.8
sketch "Sketch17" plane through (0, 0, 0) normal (0, 1, 0) x axis (1, 0, 0)
  line L1 (0, -18.8361) -> (40.0012, -18.8361)
  line L2 (0, -1.016) -> (43.18, -1.016)
  line L3 (40.0012, -18.8361) -> (43.18, -1.016)
  line L4 (0, -1.016) -> (0, -25.146)
  line L5 (0, -1.016) -> (43.18, -1.016)
  line L6 (0, -25.1861) -> (0, -1.016)
  curve K1 (0, -25.1861) -> (0, -12.4861)
  curve K2 (40.0012, -18.8361) -> (-40.0012, -18.8361)
  line L7 (0, -12.4861) -> (0, -25.146)
  closed curve K3 centre (0, -18.8361)
  point P3 (0, -1.016)
  point P6 (0, -1.016)
  point P9 (0, -1.016)
  point P10 (0, -1.016)
  point P8 (0, -12.4861)
  point P7 (0, -25.1861)
  point P14 (-40.0012, -18.8361)
  point P11 (40.0012, -18.8361)
  point P4 (43.18, -1.016)
  coincident P3 P6
  coincident P3 P9
  perpendicular L2 L4
  coincident P3 P10
  perpendicular L5 L6
  horizontal L1
  perpendicular L1 K1
  coincident P8 K3
  coincident P7 K3
  coincident K3 P14
  coincident P11 K3
  parallel K1 L7
  dimension "d17" distance P3 P4 = 43.18
revolve "Revolve4" sketch "Sketch17" AlongAngle 360
shell "Shell5" innerThickness 1.016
